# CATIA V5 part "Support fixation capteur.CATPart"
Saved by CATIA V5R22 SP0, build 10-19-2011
Part number: Support fixation capteur
Bounding box of the stored display mesh (mm): x 0 to 30, y -40 to 40, z -9.5 to 9.5
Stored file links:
  D:\PER\CAO_PER_MODIF_2025\CAO_PER_pick&place_2024P\Cadre\Support fixation capteur.CATPart
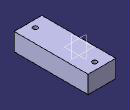
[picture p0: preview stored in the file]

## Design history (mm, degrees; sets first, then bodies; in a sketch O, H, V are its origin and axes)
Body1 (main body)
  Sketch1 on yz-plane, origin (0, 0, 0), H (0, 1, 0), V (0, 0, 1)
    line L1 (40, 9.5) -> (40, -9.5)
    line L2 (40, -9.5) -> (-40, -9.5)
    line L3 (-40, -9.5) -> (-40, 9.5)
    line L4 (-40, 9.5) -> (40, 9.5)
    length L1 = 19
    length L4 = 80
    vertical: L1 V, L3 V
    horizontal: L2 H, L4 H
    equidistance: L1 L3 O, L2 L4 O
  Pad1: profile Sketch1, direction (1, 0, 0), length 30
  Sketch2 on face of Pad1 from Sketch1.L4, origin (11.7763, 27.2391, 9.5), H (1, 0, 0), V (0, 1, 0)
    point P1 (3.2237, 4.7609)
    axis line L1 (3.2237, 25.5247) -> (3.2237, -15.785)
    reference projected line E1 (18.2237, 12.7609) -> (18.2237, -67.2391) from edge [face of Pad1 from Sketch1.L4 | end face of Pad1]
    reference projected line E2 (-11.7763, 12.7609) -> (-11.7763, -67.2391) from edge [start face of Pad1 | face of Pad1 from Sketch1.L4]
    reference projected line E3 (-11.7763, 12.7609) -> (18.2237, 12.7609) from edge [face of Pad1 from Sketch1.L4 | face of Pad1 from Sketch1.L1]
    reference intersected line E4 through (0, -27.2391) direction (-1, 0) from zx-plane
    point P6 (3.2237, -59.2391)
    distance E3 P1 = 8
    vertical: L1 V
    symmetry: E1 E2 L1, P1 P6 E4
    coincidence: P1 L1
  Hole1: placed by Sketch2, at (15, 32, 9.5) direction (0, 0, -1), diameter 4.917, through (limit type 3), threaded "M6", thread diameter 6, thread depth 10, pitch 1
  Mirror1: of Hole1, about zx-plane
